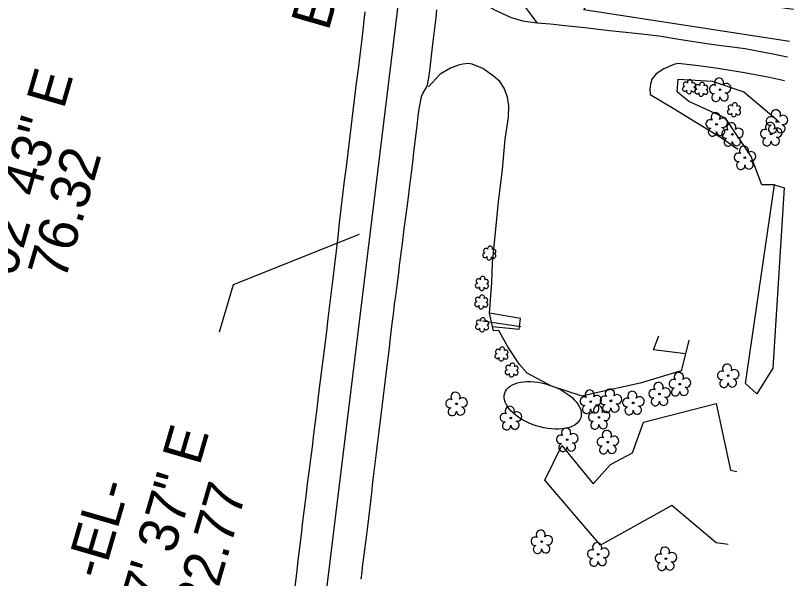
# Model space of a CAD drawing. Extents: x 479429 to 482809, y 488118 to 492379.
# Drawn here: x 481188.6 to 481504.5, y 490481.6 to 490710.2 of the extents above; entities that cross this region are included whole.
import ezdxf

# ---------------------------------------------------------------- set-up
doc = ezdxf.new("R2010")
doc.units = 0
for name, color, linetype in [('CTL Secondary Horizontal and Vertical Leader', 7, 'Continuous'), ('CTL Secondary Horizontal and Vertical Text', 7, 'Continuous'), ('Exist Horizontal Alignment', 7, 'Continuous'), ('Exist Horizontal Alignment Direction Label', 7, 'Continuous'), ('Exist Other Culture Area Outline', 7, 'Continuous'), ('Exist Other Culture Sign', 7, 'Continuous'), ('Exist Roads Change in Surface', 7, 'Continuous'), ('Exist Roads EOP', 7, 'Continuous'), ('Exist Roads EOP Other', 7, 'Continuous'), ('Exist Roads Soil', 7, 'Continuous'), ('Exist Vegetation Hedge Row', 7, 'Continuous'), ('Exist Vegetation Shrub CELL', 7, 'Continuous'), ('Exist Vegetation Tree CELL', 7, 'Continuous'), ('Exist Vegetation Woods Line', 7, 'Continuous')]:
    doc.layers.add(name, color=color, linetype=linetype)

msp = doc.modelspace()

# ---------------------------------------------------------------- linework, layer by layer
at = {"layer": 'CTL Secondary Horizontal and Vertical Leader'}
msp.add_lwpolyline([(481328.11, 490621.35), (481276.91, 490600.91), (481271.3, 490581.58)], dxfattribs=at)
at = {"layer": 'Exist Horizontal Alignment'}
msp.add_line((481201.31, 489545.89), (481397.95, 491156.7), dxfattribs=at)
at = {"layer": 'Exist Other Culture Area Outline'}
msp.add_ellipse((481402.68, 490551.89), major_axis=(-15.44, 5), ratio=0.535519, dxfattribs=at)
at = {"layer": 'Exist Other Culture Sign'}
msp.add_line((481378.28, 490586.18), (481393.85, 490583.96), dxfattribs=at)
at = {"layer": 'Exist Roads Change in Surface'}
for points in [[(481382.33, 490583.89), (481393.07, 490582.83), (481393.62, 490587.15), (481381.09, 490589.41)], [(481460.69, 490572.89), (481447.62, 490574.53), (481449.85, 490580.13)]]:
    msp.add_lwpolyline(points, dxfattribs=at)
at = {"layer": 'Exist Roads EOP'}
for points in [[(481302.13, 490478.41), (481302.77, 490483.61), (481303.4, 490488.85), (481304.04, 490494.12), (481304.66, 490499.44), (481305.29, 490504.72), (481305.92, 490509.91), (481306.56, 490515.01), (481307.19, 490520.01), (481307.83, 490524.98), (481308.47, 490530), (481309.11, 490535.07), (481309.74, 490540.18), (481310.38, 490545.32), (481311.03, 490550.5), (481311.68, 490555.7), (481312.34, 490560.92), (481313, 490566.16), (481313.65, 490571.41), (481314.3, 490576.65), (481314.94, 490581.9), (481315.58, 490587.19), (481316.23, 490592.55), (481316.88, 490597.99), (481317.54, 490603.5), (481318.21, 490609.06), (481318.88, 490614.67), (481319.54, 490620.32), (481320.2, 490626), (481320.87, 490631.71), (481321.55, 490637.42), (481322.23, 490643.12), (481322.92, 490648.81), (481323.62, 490654.5), (481324.32, 490660.17), (481325.01, 490665.83), (481325.71, 490671.48), (481326.41, 490677.12), (481327.11, 490682.79), (481327.81, 490688.47), (481328.51, 490694.17), (481329.16, 490699.55), (481329.73, 490704.26), (481330.21, 490708.31), (481330.6, 490711.69)], [(481359.57, 490712.52), (481359.2, 490709.41), (481358.83, 490706.22), (481358.44, 490702.94), (481358.06, 490699.73), (481357.37, 490693.92), (481356.79, 490689.04), (481356.36, 490685.74), (481355.88, 490682.78), (481355.69, 490682), (481355.44, 490681.34), (481353.79, 490678.57), (481353.52, 490677.94), (481353.28, 490677.24), (481352.49, 490673.06), (481352.01, 490669.51), (481351.66, 490666.75), (481351.24, 490663.26), (481350.74, 490659.03), (481350.22, 490654.66), (481349.75, 490650.72), (481349.32, 490647.21), (481348.58, 490641.25), (481347.84, 490635.42), (481347.08, 490629.48), (481346.31, 490623.55), (481345.53, 490617.62), (481344.78, 490611.68), (481344.41, 490608.7), (481344.04, 490605.69), (481343.65, 490602.62), (481343.24, 490599.5), (481342.82, 490596.31), (481342.4, 490593.14), (481342.01, 490590.05), (481341.31, 490584.14), (481340.64, 490578.27), (481340.28, 490575.23), (481339.9, 490572.13), (481339.51, 490568.97), (481339.11, 490565.74), (481338.7, 490562.45), (481338.28, 490559.1), (481337.86, 490555.73), (481337.43, 490552.39), (481337.02, 490549.09), (481336.6, 490545.8), (481336.19, 490542.54), (481335.79, 490539.26), (481335.39, 490535.99), (481335, 490532.7), (481334.62, 490529.41), (481334.23, 490526.12), (481333.85, 490522.82), (481333.46, 490519.51), (481333.08, 490516.19), (481332.68, 490512.85), (481332.28, 490509.48), (481331.87, 490506.09), (481331.45, 490502.74), (481331.05, 490499.5), (481330.66, 490496.35), (481330.29, 490493.31), (481329.91, 490490.32), (481329.54, 490487.33), (481329.16, 490484.34), (481328.79, 490481.35)]]:
    msp.add_lwpolyline(points, dxfattribs=at)
at = {"layer": 'Exist Roads EOP Other'}
for points in [[(481361.54, 490729.47), (481361.63, 490729.14), (481363.35, 490725.53), (481365.2, 490722.89), (481367.2, 490721.37), (481371.94, 490718.72), (481376.11, 490716.48), (481383.4, 490712.37), (481389.88, 490709.42), (481394.41, 490708.11), (481400.23, 490707.34), (481405.88, 490706.87), (481411.7, 490706.15), (481419.75, 490705.37), (481429.8, 490704.19), (481440.37, 490703.11), (481450.01, 490701.93), (481457.9, 490700.59), (481471.12, 490698.55), (481484.89, 490696.79), (481496.11, 490694.69), (481502.13, 490693.52)], [(481461.97, 490578.41), (481460.69, 490572.89), (481458.88, 490565.89), (481442.26, 490560.87), (481422.63, 490556.66), (481418.71, 490555.67), (481406.24, 490559.73), (481396.37, 490565.03), (481393.26, 490568.56), (481388.51, 490575.7), (481384.84, 490582.28), (481382.63, 490582.21), (481382.33, 490583.89), (481381.09, 490589.41), (481381.98, 490601.62), (481382.32, 490609.75), (481383.36, 490620.81), (481384.73, 490634.52), (481386.39, 490647.73), (481387.48, 490660.07), (481388.83, 490668.97), (481388.92, 490673.53), (481388.36, 490677.13), (481387.02, 490680.68), (481385.3, 490683.44), (481382.73, 490685.68), (481378.39, 490688.71), (481374.05, 490690.55), (481372.44, 490690.75), (481370.29, 490690.5), (481368.5, 490690.08), (481365.17, 490688.84), (481360.96, 490686.4), (481356.31, 490681.26)], [(481500.93, 490683.69), (481494.81, 490685.12), (481484.63, 490686.92), (481473.8, 490688.74), (481465.87, 490689.81), (481457.72, 490690.82), (481455.87, 490690.33), (481451.83, 490688.63), (481448.75, 490686.52), (481447, 490684.36), (481446.4, 490682.43), (481446.17, 490680.44), (481446.32, 490678.14), (481455.6, 490672.62), (481465.19, 490666.74), (481475.61, 490660.38), (481481.85, 490655.96)]]:
    msp.add_lwpolyline(points, dxfattribs=at)
at = {"layer": 'Exist Roads Soil'}
msp.add_lwpolyline([(481498.52, 490808.85), (481490.76, 490792.42), (481484.38, 490778.79), (481478.93, 490772.35), (481472.98, 490767.56), (481463.26, 490760.19), (481455.9, 490753.72), (481445.67, 490745.39), (481437.48, 490740.08), (481426.22, 490735.05), (481420.51, 490733.11), (481416.31, 490732.04), (481412.5, 490730.8), (481407.32, 490728.72), (481400.72, 490725.7), (481392.59, 490721.76), (481392.12, 490720.3), (481392.65, 490718.37), (481395.26, 490714.03), (481400.23, 490707.34)], dxfattribs=at)
at = {"layer": 'Exist Vegetation Hedge Row'}
msp.add_lwpolyline([(481496.81, 490641.54), (481491.7, 490641.5), (481487.32, 490653.02), (481476.96, 490668.5), (481462.02, 490675.39), (481457.34, 490679.19), (481457.71, 490684.37), (481471.42, 490683.6), (481484.34, 490679.19), (481497.41, 490668.35), (481498.87, 490666.79)], dxfattribs=at)
at = {"layer": 'Exist Vegetation Shrub CELL'}
for p, q in [((481462.2, 490681.14), (481462.2, 490681.14)), ((481467.14, 490680.11), (481467.14, 490680.11)), ((481480.42, 490671.8), (481480.42, 490671.8)), ((481381.07, 490613.6), (481381.07, 490613.6)), ((481378.05, 490601.27), (481378.05, 490601.27)), ((481377.8, 490593.73), (481377.8, 490593.73)), ((481378.15, 490584.47), (481378.15, 490584.47)), ((481385.98, 490572.6), (481385.98, 490572.6)), ((481390.12, 490566.1), (481390.12, 490566.1))]:
    msp.add_line(p, q, dxfattribs=at)
for centre, radius, start, end in [((481460.72, 490682.26), 0.968, 35.8908, 245.4216), ((481462.43, 490683.18), 0.99, 334.8391, 200.4717), ((481463.87, 490682.01), 0.929, 284.4567, 126.0861), ((481465.66, 490681.23), 0.968, 35.8908, 245.4216), ((481467.37, 490682.15), 0.99, 334.8391, 200.4717), ((481468.81, 490680.98), 0.929, 284.4567, 126.0861), ((481460.4, 490680.43), 0.955, 95.1099, 327.9534), ((481462.07, 490679.45), 0.984, 151.2797, 21.387), ((481463.84, 490680.21), 0.937, 204.9913, 73.4601), ((481465.34, 490679.4), 0.955, 95.1099, 327.9534), ((481467.01, 490678.42), 0.984, 151.2797, 21.387), ((481468.78, 490679.18), 0.937, 204.9913, 73.4601), ((481478.94, 490672.93), 0.968, 35.8908, 245.4216), ((481480.65, 490673.84), 0.99, 334.8391, 200.4717), ((481482.09, 490672.67), 0.929, 284.4567, 126.0861), ((481478.62, 490671.1), 0.955, 95.1099, 327.9534), ((481480.29, 490670.12), 0.984, 151.2797, 21.387), ((481482.06, 490670.87), 0.937, 204.9913, 73.4601), ((481379.59, 490614.72), 0.968, 35.8908, 245.4216), ((481381.3, 490615.64), 0.99, 334.8391, 200.4717), ((481382.75, 490614.47), 0.929, 284.4567, 126.0861), ((481379.27, 490612.89), 0.955, 95.1099, 327.9534), ((481380.94, 490611.91), 0.984, 151.2797, 21.387), ((481382.71, 490612.67), 0.937, 204.9913, 73.4601), ((481376.57, 490602.39), 0.968, 35.8908, 245.4216), ((481378.28, 490603.31), 0.99, 334.8391, 200.4717), ((481379.72, 490602.14), 0.929, 284.4567, 126.0861), ((481376.25, 490600.56), 0.955, 95.1099, 327.9534), ((481377.92, 490599.58), 0.984, 151.2797, 21.387), ((481379.69, 490600.34), 0.937, 204.9913, 73.4601), ((481378.03, 490595.77), 0.99, 334.8391, 200.4717), ((481376, 490593.02), 0.955, 95.1099, 327.9534), ((481376.32, 490594.85), 0.968, 35.8908, 245.4216), ((481379.44, 490592.8), 0.937, 204.9913, 73.4601), ((481379.47, 490594.6), 0.929, 284.4567, 126.0861), ((481377.67, 490592.04), 0.984, 151.2797, 21.387), ((481378.38, 490586.51), 0.99, 334.8391, 200.4717), ((481376.35, 490583.76), 0.955, 95.1099, 327.9534), ((481376.67, 490585.59), 0.968, 35.8908, 245.4216), ((481379.79, 490583.54), 0.937, 204.9913, 73.4601), ((481379.82, 490585.34), 0.929, 284.4567, 126.0861), ((481378.02, 490582.78), 0.984, 151.2797, 21.387), ((481384.5, 490573.73), 0.968, 35.8908, 245.4216), ((481386.21, 490574.64), 0.99, 334.8391, 200.4717), ((481387.66, 490573.47), 0.929, 284.4567, 126.0861), ((481384.18, 490571.9), 0.955, 95.1099, 327.9534), ((481385.86, 490570.92), 0.984, 151.2797, 21.387), ((481387.62, 490571.67), 0.937, 204.9913, 73.4601), ((481388.64, 490567.23), 0.968, 35.8908, 245.4216), ((481390.35, 490568.14), 0.99, 334.8391, 200.4717), ((481388.32, 490565.4), 0.955, 95.1099, 327.9534), ((481389.99, 490564.42), 0.984, 151.2797, 21.387), ((481391.76, 490565.17), 0.937, 204.9913, 73.4601), ((481391.79, 490566.97), 0.929, 284.4567, 126.0861)]:
    msp.add_arc(centre, radius, start, end, dxfattribs=at)
at = {"layer": 'Exist Vegetation Tree CELL'}
for p, q in [((481474.67, 490680.17), (481474.67, 490680.17)), ((481473.27, 490666.08), (481473.27, 490666.08)), ((481497.75, 490667.23), (481497.75, 490667.23)), ((481479.7, 490661.98), (481479.7, 490661.98)), ((481495.43, 490662.12), (481495.43, 490662.12)), ((481484.76, 490652.49), (481484.76, 490652.49)), ((481477.96, 490563.95), (481477.96, 490563.95)), ((481458.34, 490560.53), (481458.34, 490560.53)), ((481450.1, 490556.51), (481450.1, 490556.51)), ((481367.64, 490552.53), (481367.64, 490552.53)), ((481422.15, 490553.45), (481422.15, 490553.45)), ((481430.33, 490553.78), (481430.33, 490553.78)), ((481439.43, 490552.92), (481439.43, 490552.92)), ((481389.7, 490546.79), (481389.7, 490546.79)), ((481425.53, 490547.04), (481425.53, 490547.04)), ((481412.59, 490537.95), (481412.59, 490537.95)), ((481429.12, 490536.97), (481429.12, 490536.97)), ((481402.24, 490496.56), (481402.24, 490496.56)), ((481425.17, 490491.42), (481425.17, 490491.42)), ((481452.69, 490489.63), (481452.69, 490489.63))]:
    msp.add_line(p, q, dxfattribs=at)
for centre in [(481474.67, 490680.17), (481473.27, 490666.08), (481497.75, 490667.23), (481479.7, 490661.98), (481495.43, 490662.12), (481484.76, 490652.49), (481477.96, 490563.95), (481458.34, 490560.53), (481450.1, 490556.51), (481367.64, 490552.53), (481422.15, 490553.45), (481430.33, 490553.78), (481439.43, 490552.92), (481389.7, 490546.79), (481425.53, 490547.04), (481412.59, 490537.95), (481429.12, 490536.97), (481402.24, 490496.56), (481425.17, 490491.42), (481452.69, 490489.63)]:
    msp.add_circle(centre, 0.326, dxfattribs=at)
for centre, radius, start, end in [((481474.29, 490683.04), 1.86, 330.1651, 219.7134), ((481472.07, 490680.32), 1.73, 62.6636, 279.3457), ((481477.22, 490680.76), 1.9, 257.1011, 134.1999), ((481472.97, 490677.05), 1.69, 111.5671, 6.231), ((481476.35, 490677.27), 1.7, 181.2822, 74.56), ((481472.89, 490668.95), 1.86, 330.1651, 219.7134), ((481495.14, 490667.38), 1.73, 62.6636, 279.3457), ((481497.36, 490670.1), 1.86, 330.1651, 219.7134), ((481500.3, 490667.82), 1.9, 257.1011, 134.1999), ((481470.67, 490666.23), 1.73, 62.6636, 279.3457), ((481475.82, 490666.67), 1.9, 257.1011, 134.1999), ((481479.31, 490664.85), 1.86, 330.1651, 219.7134), ((481495.05, 490664.99), 1.86, 330.1651, 219.7134), ((481499.42, 490664.33), 1.7, 181.2822, 74.56), ((481471.57, 490662.96), 1.69, 111.5671, 6.231), ((481474.95, 490663.18), 1.7, 181.2822, 74.56), ((481477.09, 490662.14), 1.73, 62.6636, 279.3457), ((481482.24, 490662.57), 1.9, 257.1011, 134.1999), ((481492.83, 490662.27), 1.73, 62.6636, 279.3457), ((481496.05, 490664.11), 1.69, 111.5671, 6.231), ((481497.98, 490662.71), 1.9, 257.1011, 134.1999), ((481477.99, 490658.86), 1.69, 111.5671, 6.231), ((481481.37, 490659.08), 1.7, 181.2822, 74.56), ((481493.73, 490659), 1.69, 111.5671, 6.231), ((481497.11, 490659.22), 1.7, 181.2822, 74.56), ((481484.38, 490655.37), 1.86, 330.1651, 219.7134), ((481482.16, 490652.65), 1.73, 62.6636, 279.3457), ((481487.31, 490653.08), 1.9, 257.1011, 134.1999), ((481483.06, 490649.37), 1.69, 111.5671, 6.231), ((481486.44, 490649.59), 1.7, 181.2822, 74.56), ((481477.58, 490566.82), 1.86, 330.1651, 219.7134), ((481457.96, 490563.41), 1.86, 330.1651, 219.7134), ((481475.36, 490564.1), 1.73, 62.6636, 279.3457), ((481480.51, 490564.54), 1.9, 257.1011, 134.1999), ((481455.74, 490560.69), 1.73, 62.6636, 279.3457), ((481460.89, 490561.12), 1.9, 257.1011, 134.1999), ((481476.26, 490560.83), 1.69, 111.5671, 6.231), ((481479.64, 490561.05), 1.7, 181.2822, 74.56), ((481429.94, 490556.65), 1.86, 330.1651, 219.7134), ((481449.71, 490559.38), 1.86, 330.1651, 219.7134), ((481452.64, 490557.1), 1.9, 257.1011, 134.1999), ((481456.64, 490557.41), 1.69, 111.5671, 6.231), ((481460.02, 490557.63), 1.7, 181.2822, 74.56), ((481367.26, 490555.4), 1.86, 330.1651, 219.7134), ((481419.55, 490553.61), 1.73, 62.6636, 279.3457), ((481421.77, 490556.33), 1.86, 330.1651, 219.7134), ((481424.7, 490554.04), 1.9, 257.1011, 134.1999), ((481427.72, 490553.93), 1.73, 62.6636, 279.3457), ((481432.88, 490554.37), 1.9, 257.1011, 134.1999), ((481439.04, 490555.79), 1.86, 330.1651, 219.7134), ((481441.98, 490553.5), 1.9, 257.1011, 134.1999), ((481447.49, 490556.66), 1.73, 62.6636, 279.3457), ((481365.04, 490552.68), 1.73, 62.6636, 279.3457), ((481370.19, 490553.11), 1.9, 257.1011, 134.1999), ((481423.83, 490550.55), 1.7, 181.2822, 74.56), ((481428.62, 490550.66), 1.69, 111.5671, 6.231), ((481432, 490550.88), 1.7, 181.2822, 74.56), ((481436.82, 490553.07), 1.73, 62.6636, 279.3457), ((481448.39, 490553.39), 1.69, 111.5671, 6.231), ((481451.77, 490553.61), 1.7, 181.2822, 74.56), ((481365.94, 490549.4), 1.69, 111.5671, 6.231), ((481369.32, 490549.63), 1.7, 181.2822, 74.56), ((481389.32, 490549.67), 1.86, 330.1651, 219.7134), ((481392.25, 490547.38), 1.9, 257.1011, 134.1999), ((481420.45, 490550.33), 1.69, 111.5671, 6.231), ((481425.15, 490549.92), 1.86, 330.1651, 219.7134), ((481428.08, 490547.63), 1.9, 257.1011, 134.1999), ((481437.72, 490549.79), 1.69, 111.5671, 6.231), ((481441.1, 490550.02), 1.7, 181.2822, 74.56), ((481387.1, 490546.95), 1.73, 62.6636, 279.3457), ((481422.93, 490547.2), 1.73, 62.6636, 279.3457), ((481388, 490543.67), 1.69, 111.5671, 6.231), ((481391.38, 490543.89), 1.7, 181.2822, 74.56), ((481412.2, 490540.82), 1.86, 330.1651, 219.7134), ((481423.83, 490543.92), 1.69, 111.5671, 6.231), ((481427.21, 490544.14), 1.7, 181.2822, 74.56), ((481409.98, 490538.11), 1.73, 62.6636, 279.3457), ((481415.14, 490538.54), 1.9, 257.1011, 134.1999), ((481428.73, 490539.85), 1.86, 330.1651, 219.7134), ((481410.88, 490534.83), 1.69, 111.5671, 6.231), ((481414.26, 490535.05), 1.7, 181.2822, 74.56), ((481426.51, 490537.13), 1.73, 62.6636, 279.3457), ((481431.67, 490537.56), 1.9, 257.1011, 134.1999), ((481427.41, 490533.85), 1.69, 111.5671, 6.231), ((481430.79, 490534.07), 1.7, 181.2822, 74.56), ((481399.63, 490496.71), 1.73, 62.6636, 279.3457), ((481401.85, 490499.43), 1.86, 330.1651, 219.7134), ((481404.79, 490497.15), 1.9, 257.1011, 134.1999), ((481403.91, 490493.66), 1.7, 181.2822, 74.56), ((481424.78, 490494.3), 1.86, 330.1651, 219.7134), ((481400.54, 490493.44), 1.69, 111.5671, 6.231), ((481422.56, 490491.58), 1.73, 62.6636, 279.3457), ((481427.72, 490492.01), 1.9, 257.1011, 134.1999), ((481452.3, 490492.51), 1.86, 330.1651, 219.7134), ((481455.24, 490490.22), 1.9, 257.1011, 134.1999), ((481423.46, 490488.3), 1.69, 111.5671, 6.231), ((481426.84, 490488.52), 1.7, 181.2822, 74.56), ((481450.08, 490489.79), 1.73, 62.6636, 279.3457), ((481450.98, 490486.51), 1.69, 111.5671, 6.231), ((481454.36, 490486.73), 1.7, 181.2822, 74.56)]:
    msp.add_arc(centre, radius, start, end, dxfattribs=at)
at = {"layer": 'Exist Vegetation Woods Line'}
for points in [[(481502.88, 490699.66), (481419.33, 490712.53), (481426.78, 490724.26), (481504.49, 490712.84)], [(481500.73, 490640.31), (481496.18, 490566.97), (481489.57, 490556.6), (481485.01, 490560.84), (481496.81, 490641.54)], [(481496.81, 490641.54), (481500.73, 490640.31)], [(481477.94, 490495.39), (481473.12, 490496.12), (481455.16, 490511.21), (481426.18, 490495.14), (481403.49, 490521.51), (481410.41, 490535.67), (481423.11, 490520.06), (481430.16, 490527.88), (481439.2, 490532.68), (481443.6, 490545.08), (481473.11, 490552.73), (481478.87, 490525.58), (481481.56, 490525.08)]]:
    msp.add_lwpolyline(points, dxfattribs=at)

# ---------------------------------------------------------------- texts
at = {"layer": 'CTL Secondary Horizontal and Vertical Text'}
msp.add_text('BL-101', height=16, rotation=73.904, dxfattribs=at).set_placement((481315.61, 490703.6))
at = {"layer": 'Exist Horizontal Alignment Direction Label'}
for s, p in [('S 83%%d 02\' 43" E', (481171.98, 490547.3)), ('76.32', (481208.66, 490602.23)), ('N 6%%d 57\' 37" E', (481230.12, 490412.81)), ('-EL-', (481223.93, 490480.7)), ('1,622.77', (481259.4, 490437.61))]:
    msp.add_text(s, height=16, rotation=73.8069, dxfattribs=at).set_placement(p)

doc.saveas('drawing.dxf')
